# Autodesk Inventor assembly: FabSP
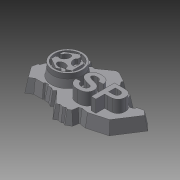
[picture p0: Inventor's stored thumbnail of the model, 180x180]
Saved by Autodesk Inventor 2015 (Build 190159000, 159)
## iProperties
Created: 2015-04
Part Number: FabSP
Document SubType Name: Assembly
Designer: User
Author: User
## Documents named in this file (4)
- D:\Inventor_Projects\table\FabSP.iam
- D:\Inventor_Projects\table\l_singapore.ipt
- D:\Inventor_Projects\table\FabLabLogo.ipt
- D:\Inventor_Projects\table\SP.ipt
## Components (3 placed, 3 different names)
1. l_singapore:1 — Mate:2, Mate:3
2. SP:1 — Mate:2
3. FabLabLogo:1 — Mate:3
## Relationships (2: Mate 2)
- Mate:2: l_singapore:1 ↔ SP:1
- Mate:3: l_singapore:1 ↔ FabLabLogo:1
